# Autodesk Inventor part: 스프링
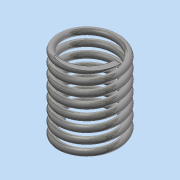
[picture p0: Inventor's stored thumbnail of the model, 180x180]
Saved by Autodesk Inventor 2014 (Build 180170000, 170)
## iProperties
Created: 2015-01
Part Number: 스프링
Material: 강철, 탄소
Document SubType Name: Modeling
Designer: net
Mass: 80.1298 g
Surface Area: 103.259 cm^2
Volume: 10.1817 cm^3
Density: 7.87 g/cm^3
Appearance: 반연마
Author: net
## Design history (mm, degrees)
sketch "스케치1"
  geometry: L1 (0, 0)-(0, 35.235); L2 (25, -89.64)-(-25, -89.64) reference; L3 (-20, -138.14)-(20, -138.14) reference; C1 r 2 at (17.5, -138.14); C2 r 2 at (17.5, -89.64)
  constraints: 2 centre point, 2 end point, 2 point on line, 1 equal radius, 1 vertical, 1 vertical alignment
  dimensions: "d1" = 4 diameter of C2; "d2" = 48.5 distance of C1.centre C2.centre (derived); "d3" = 35 diameter of C1.centre L1
feature "코일1" sketch "스케치1" pitch "d4" = 10; turns "d6" = 7.5; dims "d5" = 48.5 (= d2), "d7" = 0, angle "d8" = 90 deg, angle "d9" = 90 deg, "d10" = 0, "d11" = 0
sketch "스케치2"
  geometry: L1 (-50.551, 64.006)-(16.389, 64.006); L2 (16.389, 64.006)-(16.389, 48.5); L3 (16.389, 48.5)-(-50.551, 48.5); L4 (-50.551, 48.5)-(-50.551, 64.006); L5 (-50.551, 0)-(24.583, 0); L6 (24.583, 0)-(24.583, -11.346); L7 (24.583, -11.346)-(-50.551, -11.346); L8 (-50.551, -11.346)-(-50.551, 0); 5 further points
  constraints: 16 end point, 4 parallel, 2 horizontal, 2 horizontal alignment, 2 perpendicular, 2 point on line
extrude "돌출1" cut sketch "스케치2" stored distance "d12" = 140.25; taper "d13" = 0 deg
node "솔리드1"
node "투영된 루프1"
node "참조1"
node "참조2"
